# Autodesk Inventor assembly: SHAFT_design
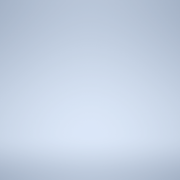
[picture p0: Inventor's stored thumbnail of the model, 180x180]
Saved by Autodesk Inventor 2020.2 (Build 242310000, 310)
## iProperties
Created: 2020-01
Part Number: SHAFT_design
Document SubType Name: Assembly
Designer: thira
Author: thira
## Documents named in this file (1)
- F:\99.โปรแกรมอัดหน้าจอ\Synergysoft\SHAFT_design.iam
